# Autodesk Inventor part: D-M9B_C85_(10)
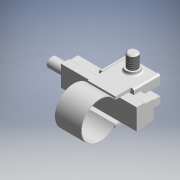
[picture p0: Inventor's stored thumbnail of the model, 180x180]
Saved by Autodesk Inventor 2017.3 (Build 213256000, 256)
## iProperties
Part Number: D-M9B_C85_(10)
Material: Generic
Catalog Web Link: www.cadenas.de
Description: C85/CD85 SW-ISO Standard Air Cylinder:Standard Type Double Acting Single Rod
Vendor: SMC
Document SubType Name: Modeling
Designer: partserver
Manufacturer: SMC
Mass: 1.38436 g
Surface Area: 19.8684 cm^2
Volume: 1.38436 cm^3
Density: 1 g/cm^3
Appearance: PSOLRGB-255-255-255
Category: PARTsolutions
Company: SMC
Title: D-M9B_C85
Author: Cadenas PARTsolutions
Comments: ISO Standard Air Cylinder:Standard Type Double Acting Single Rod
PSOL_IDENT_0: {$CADENAS_DATA\23d-libs\smc_jp\actuator\standard_air_cylinder\c85\c85\parts\c85_sw_band.prj},174 {VT
PSOL_IDENT_1: YP=3D},{NB=D-M9B_C85_(10)},{LINA=D-M9B_C85},{NN=C85/CD85 SW},{DATE=09.12.2020 02:57:06},{GEOMDATE=03
PSOL_IDENT_2: .08.2017 08:12:00},{VERSION=},{LINEID=20},{WBVAR=AUTOSW},{WBNUMERIC=}  {NB=D-M9B_C85_(10)},{LINA=D-M
PSOL_IDENT_3: 9B_C85},{KT=DUMMY},{BORE=10.000},{AUTOSW=-M9B},{ASN=A},{SWITCHS=F},{HS=7.6},{ORDER=D-M9B_C85},{D1=11
PSOL_IDENT_4: .000}
NB: D-M9B_C85_(10)
NN: C85/CD85 SW
NT: ISO Standard Air Cylinder:Standard Type Double Acting Single Rod
NBSYN: $ORDER._($BORE.)
LINA: D-M9B_C85
CATALOG: SMC (JP
BORE: 10
AUTOSW: M9B
D1: 11
SUPPLIER: SMC
ARTICLENO: D-M9B_C85_(10)
BOMINFO: D-M9B_C85
CREATOR: CADENAS GmbH
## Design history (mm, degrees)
sketch "Sketch_14"
  geometry: L1 (3, 1.5)-(6, 1.5); L2 (6.5, 1)-(6.5, -1); L3 (6, -1.5)-(3, -1.5); L4 (3, -1.5)-(3, -3.75); L5 (3.5, -4.25)-(4, -4.25); L6 (4, -4.25)-(4, -3.25); L7 (4, -3.25)-(12.6, -3.25); L8 (12.6, -3.25)-(12.6, -4.25); L9 (12.6, -4.25)-(13.1, -4.25); L10 (13.6, -3.75)-(13.6, -1.5); L11 (13.6, -1.5)-(10.6, -1.5); L12 (10.1, -1)-(10.1, 1); L13 (10.6, 1.5)-(13.6, 1.5); L14 (13.6, 1.5)-(13.6, 3.75); L15 (13.1, 4.25)-(12.6, 4.25); L16 (12.6, 4.25)-(12.6, 3.25); L17 (12.6, 3.25)-(4, 3.25); L18 (4, 3.25)-(4, 4.25); L19 (4, 4.25)-(3.5, 4.25); L20 (3, 3.75)-(3, 1.5); A1 r 0.5 centre (6, 1) between (6.5, 1) and (6, 1.5); A2 r 0.5 centre (6, -1) between (6, -1.5) and (6.5, -1); A3 r 0.5 centre (3.5, -3.75) between (3, -3.75) and (3.5, -4.25); A4 r 0.5 centre (13.1, -3.75) between (13.1, -4.25) and (13.6, -3.75); A5 r 0.5 centre (10.6, -1) between (10.1, -1) and (10.6, -1.5); A6 r 0.5 centre (10.6, 1) between (10.6, 1.5) and (10.1, 1); A7 r 0.5 centre (13.1, 3.75) between (13.6, 3.75) and (13.1, 4.25); A8 r 0.5 centre (3.5, 3.75) between (3.5, 4.25) and (3, 3.75)
  constraints: 40 end point, 16 point on circle, 8 centre point
extrude "Extrusion1" join sketch "Sketch_14" distance "d0" = 8; taper "d1" = 0 deg
sketch "Sketch_13"
  geometry: L1 (1.4, 2.8)-(1.4, -2.8); L2 (1.4, -2.8)-(2.9, -2.8); L3 (2.9, -2.8)-(2.9, -1.7); L4 (2.9, -1.7)-(3.4, -1.7); L5 (3.4, -1.7)-(3.4, 1.7); L6 (3.4, 1.7)-(2.9, 1.7); L7 (2.9, 1.7)-(2.9, 2.8); L8 (2.9, 2.8)-(1.4, 2.8)
  constraints: 16 end point
extrude "Extrusion2" cut sketch "Sketch_13" distance "d2" = 20; taper "d3" = 0 deg
sketch "Sketch_12"
  geometry: L1 (-3.175, -2.3)-(3.175, -2.3); L2 (3.175, -2.3)-(3.175, -0.01); L3 (2.775, 0.79)-(2.775, 2.9); L4 (2.775, 2.9)-(-2.775, 2.9); L5 (-2.775, 2.9)-(-2.775, 0.79); L6 (-3.175, -0.01)-(-3.175, -2.3); A1 r 1 centre (3.775, 0.79) between (2.775, 0.79) and (3.175, -0.01); A2 r 1 centre (-3.775, 0.79) between (-3.175, -0.01) and (-2.775, 0.79)
  constraints: 12 end point, 4 point on circle, 2 centre point
extrude "Extrusion3" join sketch "Sketch_12" distance "d4" = 23; taper "d5" = 0 deg
sketch "Sketch_8"
  geometry: L1 (1.323, -1.5)-(3.1, -1.5); L2 (3.1, -1.5)-(3.1, 1.5); L3 (3.1, 1.5)-(1.323, 1.5); A1 r 2 centre (0, 0) between (1.323, 1.5) and (1.323, -1.5)
  constraints: 6 end point, 2 point on circle, 1 centre point
extrude "Extrusion4" cut sketch "Sketch_8" distance "d6" = 22; taper "d7" = 0 deg
sketch "Sketch_19"
  geometry: L1 (1.428, -1.4)-(2.6, -1.4); L2 (2.6, -1.4)-(2.6, 1.4); L3 (2.6, 1.4)-(1.428, 1.4); A1 r 2 centre (0, 0) between (1.428, 1.4) and (1.428, -1.4)
  constraints: 6 end point, 2 point on circle, 1 centre point
extrude "Extrusion5" join sketch "Sketch_19" distance "d8" = 22; taper "d9" = 0 deg
sketch "Sketch_5"
  geometry: C1 r 1.2 at (2, 0); C2 r 1 at (2, 0); 2 further points
  constraints: 2 centre point
extrude "Extrusion6" cut sketch "Sketch_5" stored distance "d10" = 2; taper "d11" = 0 deg
sketch "Sketch_6"
  geometry: L1 (1.492, -0.861)-(2.861, 0.508); L2 (2.508, 0.861)-(1.139, -0.508); A1 r 1 centre (2, 0) between (1.139, -0.508) and (1.492, -0.861); A2 r 1 centre (2, 0) between (2.861, 0.508) and (2.508, 0.861)
  constraints: 4 end point, 4 point on circle, 2 centre point
extrude "Extrusion7" cut sketch "Sketch_6" stored distance "d12" = 1; taper "d13" = 0 deg
sketch "Sketch_26"
  geometry: L1 (8.15, 0.5)-(8.15, -0.5); L2 (8.4, -0.75)-(10.6, -0.75); L3 (10.85, -0.5)-(10.85, 0.5); L4 (10.6, 0.75)-(8.4, 0.75); A1 r 0.25 centre (8.4, -0.5) between (8.15, -0.5) and (8.4, -0.75); A2 r 0.25 centre (10.6, -0.5) between (10.6, -0.75) and (10.85, -0.5); A3 r 0.25 centre (10.6, 0.5) between (10.85, 0.5) and (10.6, 0.75); A4 r 0.25 centre (8.4, 0.5) between (8.4, 0.75) and (8.15, 0.5)
  constraints: 8 end point, 8 point on circle, 4 centre point
extrude "Extrusion8" cut sketch "Sketch_26" stored distance "d14" = 0.2; taper "d15" = 0 deg
sketch "Sketch_21"
  geometry: L1 (0.25, 1.35)-(-0.25, 1.35); L2 (-0.25, -1.35)-(0.25, -1.35); A1 r 1.35 centre (-0.25, 0) between (-0.25, 1.35) and (-0.25, -1.35); A2 r 1.35 centre (0.25, 0) between (0.25, -1.35) and (0.25, 1.35)
  constraints: 4 end point, 4 point on circle, 2 centre point
extrude "Extrusion9" join sketch "Sketch_21" distance "d16" = 27; taper "d17" = 0 deg
sketch "Sketch_7"
  geometry: L1 (3.45, -3.563)-(3.45, 8.8); L2 (3.45, 8.8)-(3.25, 8.8); L3 (3.25, 8.8)-(3.25, -3.663); L4 (-3.175, -3.609)-(-3.175, 8.8); L5 (-3.175, 8.8)-(-3.375, 8.8); L6 (-3.375, 8.8)-(-3.375, -3.507); A1 r 5.7 centre (0, -8.1) between (-3.375, -3.507) and (3.45, -3.563); A2 r 5.5 centre (0, -8.1) between (-3.175, -3.609) and (3.25, -3.663)
  constraints: 12 end point, 4 point on circle, 2 centre point
extrude "Extrusion10" join sketch "Sketch_7" stored distance "d18" = 8; taper "d19" = 0 deg
sketch "Sketch_15"
  geometry: L1 (3.25, 8.8)-(3.25, -3.663); L2 (3.25, -3.663)-(4.15, -3.663); L3 (4.15, -3.663)-(4.15, 8.8); L4 (4.15, 8.8)-(3.25, 8.8)
  constraints: 8 end point
extrude "Extrusion11" join sketch "Sketch_15" stored distance "d20" = 8.5; taper "d21" = 0 deg
sketch "Sketch_16"
  geometry: L1 (-4.15, 8.8)-(-4.15, -3.663); L2 (-4.15, -3.663)-(-3.25, -3.663); L3 (-3.25, -3.663)-(-3.25, 8.8); L4 (-3.25, 8.8)-(-4.15, 8.8)
  constraints: 8 end point
extrude "Extrusion12" join sketch "Sketch_16" stored distance "d22" = 8.5; taper "d23" = 0 deg
sketch "Sketch_17"
  geometry: L1 (9.05, 5.8)-(-7.45, 5.8); L2 (-7.45, 5.8)-(-7.45, 6.55); L3 (-5.45, 8.55)-(-4.15, 8.55); L4 (-4.15, 8.55)-(-4.15, 7.3); L5 (-4.15, 7.3)-(4.15, 7.3); L6 (4.15, 7.3)-(4.15, 8.3); L7 (4.65, 7.8)-(5.15, 7.8); L8 (5.15, 7.8)-(5.15, 7.3); L9 (5.15, 7.3)-(8.743, 7.3); L10 (8.743, 7.3)-(9.05, 6.994); L11 (9.05, 6.994)-(9.05, 5.8); L12 (9.05, 5.8)-(-7.45, 5.8); A1 r 2 centre (-5.45, 6.55) between (-5.45, 8.55) and (-7.45, 6.55); A2 r 0.5 centre (4.65, 8.3) between (4.15, 8.3) and (4.65, 7.8)
  constraints: 24 end point, 4 point on circle, 2 centre point
revolve "Revolution1" sketch "Sketch_17" stored, may be unused: angle "d24" = 360 deg
thread "Thread1" dims "d25" = 3.5935, "d26" = 0
sketch "Sketch_18"
  geometry: L1 (-2, 0.343)-(-2, -0.343); L2 (-2, -0.343)-(-1.342, -0.343); L3 (-0.343, -1.342)-(-0.343, -2); L4 (-0.343, -2)-(0.343, -2); L5 (0.343, -2)-(0.343, -1.342); L6 (1.342, -0.343)-(2, -0.343); L7 (2, -0.343)-(2, 0.343); L8 (2, 0.343)-(1.342, 0.343); L9 (0.343, 1.342)-(0.343, 2); L10 (0.343, 2)-(-0.343, 2); L11 (-0.343, 2)-(-0.343, 1.342); L12 (-1.342, 0.343)-(-2, 0.343); A1 r 1 centre (-1.343, -1.343) between (-0.343, -1.342) and (-1.342, -0.343); A2 r 1 centre (1.343, -1.343) between (1.342, -0.343) and (0.343, -1.342); A3 r 1 centre (1.343, 1.343) between (0.343, 1.342) and (1.342, 0.343); A4 r 1 centre (-1.343, 1.343) between (-1.342, 0.343) and (-0.343, 1.342)
  constraints: 24 end point, 8 point on circle, 4 centre point
extrude "Extrusion13" cut sketch "Sketch_18" distance "d27" = 1.5; taper "d28" = 0 deg
node "SW_XY"
node "SW_YZ"
node "SW_ZX"
node "SW_X"
node "SW_Y"
node "SW_Z"
node "SW_Center"
body "Solid1"
